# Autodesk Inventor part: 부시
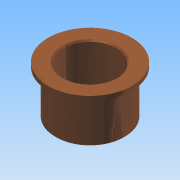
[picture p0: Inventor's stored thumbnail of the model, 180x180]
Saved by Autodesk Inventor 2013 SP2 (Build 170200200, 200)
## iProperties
Created: 2013-06
Part Number: 부시
Document SubType Name: Modeling
Designer: SeoGD™[esajin.kr]
Density: 7.86 g/cm^3
Material: 강철, 연강
Mass: 246.97 g
Surface Area: 129.264 cm^2
Volume: 31.4212 cm^3
Author: SeoGD™[esajin.kr]
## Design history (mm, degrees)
sketch "스케치1"
  geometry: C1 r 31 at (0, 0) reference; C2 r 25 at (0, 0) reference; C3 r 30 at (0, 0) reference; 1 further point
  node "참조1"
  node "참조2"
  node "참조4"
extrude "돌출1" new body sketch "스케치1" distance "d0" = 3; taper "d1" = 0 deg
extrude "돌출2" join sketch "스케치1" distance "d2" = 35; taper "d3" = 0 deg
chamfer "모따기1" distance "d6" = 1; stored, may be unused: second distance "d7" = 2, angle "d8" = 45 deg
sketch "스케치3"
  geometry: C1 r 19 at (0, 0); 1 further point
  constraints: 1 centre point, 1 coincident
  dimensions: "d13" = 38 diameter of C1
extrude "돌출4" cut sketch "스케치3" stored distance "d14" = 10; taper "d15" = 0 deg
chamfer "모따기3" distance "d16" = 1; stored, may be unused: second distance "d17" = 2, angle "d18" = 45 deg
node "솔리드1"
